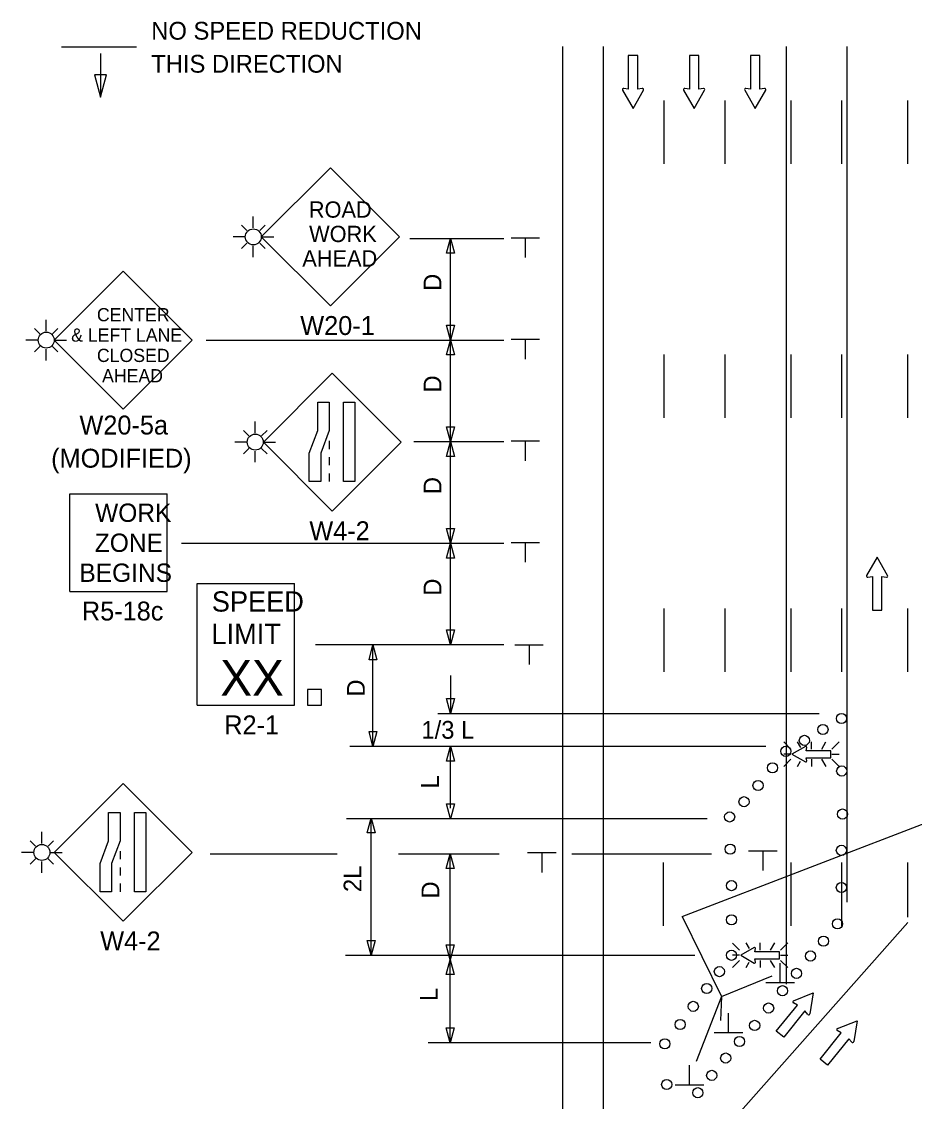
# Model space of a CAD drawing. Extents: x 16726 to 19504, y 5932 to 7446.
# Drawn here: x 16725.6 to 17077.3, y 6450.1 to 6875.1 of the extents above; entities that cross this region are included whole.
import ezdxf

# ---------------------------------------------------------------- set-up
doc = ezdxf.new("R2010")
doc.units = 0
for name, color, linetype in [('ALI_LEGAL_EX', 7, 'Continuous'), ('MT_SCRATCH_LEVEL_E', 7, 'Continuous'), ('PAVT_EDGE_EX', 7, 'Continuous'), ('TRAFFIC_SIGNS_PR', 7, 'Continuous'), ('TYPICAL_EX', 7, 'Continuous'), ('TYPICAL_TEXT_DIMEN_PR', 7, 'Continuous')]:
    doc.layers.add(name, color=color, linetype=linetype)

msp = doc.modelspace()

# ---------------------------------------------------------------- linework, layer by layer
at = {"layer": 'ALI_LEGAL_EX'}
for points in [[(16978.71, 6819.12), (16978.71, 6844.12)], [(17002.71, 6819.12), (17002.71, 6844.12)], [(17028.71, 6819.12), (17028.71, 6844.12)], [(17048.71, 6819.12), (17048.71, 6844.12)], [(17074.71, 6819.12), (17074.71, 6844.12)], [(16978.71, 6719.12), (16978.71, 6744.12)], [(17002.71, 6719.12), (17002.71, 6744.12)], [(17028.71, 6719.12), (17028.71, 6744.12)], [(17048.71, 6719.12), (17048.71, 6744.12)], [(17074.71, 6719.12), (17074.71, 6744.12)], [(16978.71, 6619.12), (16978.71, 6644.12)], [(17002.71, 6619.12), (17002.71, 6644.12)], [(17028.71, 6619.12), (17028.71, 6644.12)], [(17048.71, 6619.12), (17048.71, 6644.12)], [(17074.71, 6619.12), (17074.71, 6644.12)], [(16978.5, 6519.12), (16978.5, 6544.12)], [(17028.71, 6519.12), (17028.71, 6544.12)], [(17048.71, 6519.12), (17048.71, 6544.12)], [(17074.71, 6522.64), (17074.71, 6544.12)]]:
    msp.add_lwpolyline(points, dxfattribs=at)
at = {"layer": 'MT_SCRATCH_LEVEL_E'}
for p, q in [((16968.31, 6861.76), (16964.57, 6861.76)), ((16964.57, 6861.76), (16964.57, 6848.5)), ((16968.31, 6861.76), (16964.57, 6861.76)), ((16964.57, 6861.76), (16964.57, 6848.5)), ((16968.31, 6848.5), (16968.31, 6861.76)), ((16968.31, 6848.5), (16968.31, 6861.76)), ((16992.38, 6861.76), (16988.64, 6861.76)), ((16988.64, 6861.76), (16988.64, 6848.5)), ((16992.38, 6861.76), (16988.64, 6861.76)), ((16988.64, 6861.76), (16988.64, 6848.5)), ((16992.38, 6848.5), (16992.38, 6861.76)), ((16992.38, 6848.5), (16992.38, 6861.76)), ((17016.45, 6861.76), (17012.71, 6861.76)), ((17012.71, 6861.76), (17012.71, 6848.5)), ((17016.45, 6861.76), (17012.71, 6861.76)), ((17012.71, 6861.76), (17012.71, 6848.5)), ((17016.45, 6848.5), (17016.45, 6861.76)), ((17016.45, 6848.5), (17016.45, 6861.76)), ((16962.31, 6848.13), (16966.46, 6840.89)), ((16962.31, 6848.13), (16966.46, 6840.89)), ((16964.57, 6848.5), (16962.79, 6848.82)), ((16964.57, 6848.5), (16962.79, 6848.82)), ((16966.46, 6840.89), (16970.57, 6848.13)), ((16966.46, 6840.89), (16970.57, 6848.13)), ((16970.08, 6848.82), (16968.31, 6848.5)), ((16970.08, 6848.82), (16968.31, 6848.5)), ((16986.38, 6848.13), (16990.53, 6840.89)), ((16986.38, 6848.13), (16990.53, 6840.89)), ((16988.64, 6848.5), (16986.86, 6848.82)), ((16988.64, 6848.5), (16986.86, 6848.82)), ((16990.53, 6840.89), (16994.64, 6848.13)), ((16990.53, 6840.89), (16994.64, 6848.13)), ((16994.16, 6848.82), (16992.38, 6848.5)), ((16994.16, 6848.82), (16992.38, 6848.5)), ((17010.45, 6848.13), (17014.6, 6840.89)), ((17010.45, 6848.13), (17014.6, 6840.89)), ((17012.71, 6848.5), (17010.93, 6848.82)), ((17012.71, 6848.5), (17010.93, 6848.82)), ((17014.6, 6840.89), (17018.71, 6848.13)), ((17014.6, 6840.89), (17018.71, 6848.13)), ((17018.23, 6848.82), (17016.45, 6848.5)), ((17018.23, 6848.82), (17016.45, 6848.5)), ((17062.58, 6664.37), (17058.47, 6657.13)), ((17062.58, 6664.37), (17058.47, 6657.13)), ((17066.73, 6657.13), (17062.58, 6664.37)), ((17066.73, 6657.13), (17062.58, 6664.37)), ((17058.95, 6656.44), (17060.73, 6656.76)), ((17058.95, 6656.44), (17060.73, 6656.76)), ((17060.73, 6656.76), (17060.73, 6643.5)), ((17060.73, 6656.76), (17060.73, 6643.5)), ((17064.47, 6643.5), (17064.47, 6656.76)), ((17064.47, 6656.76), (17066.25, 6656.44)), ((17064.47, 6643.5), (17064.47, 6656.76)), ((17064.47, 6656.76), (17066.25, 6656.44)), ((17060.73, 6643.5), (17064.47, 6643.5)), ((17060.73, 6643.5), (17064.47, 6643.5)), ((17029.66, 6489.71), (17037.44, 6492.75)), ((17029.66, 6489.71), (17037.44, 6492.75)), ((17037.44, 6492.75), (17036.1, 6484.53)), ((17037.44, 6492.75), (17036.1, 6484.53)), ((17022.88, 6477.68), (17031.19, 6488.01)), ((17022.88, 6477.68), (17031.19, 6488.01)), ((17031.19, 6488.01), (17029.61, 6488.88)), ((17031.19, 6488.01), (17029.61, 6488.88)), ((17034.1, 6485.66), (17025.79, 6475.33)), ((17034.1, 6485.66), (17025.79, 6475.33)), ((17035.29, 6484.3), (17034.1, 6485.66)), ((17035.29, 6484.3), (17034.1, 6485.66)), ((17046.96, 6478.77), (17054.73, 6481.8)), ((17046.96, 6478.77), (17054.73, 6481.8)), ((17054.73, 6481.8), (17053.39, 6473.59)), ((17054.73, 6481.8), (17053.39, 6473.59)), ((17025.79, 6475.33), (17022.88, 6477.68)), ((17025.79, 6475.33), (17022.88, 6477.68)), ((17040.17, 6466.74), (17048.49, 6477.06)), ((17040.17, 6466.74), (17048.49, 6477.06)), ((17051.4, 6474.72), (17043.09, 6464.39)), ((17051.4, 6474.72), (17043.09, 6464.39)), ((17048.49, 6477.06), (17046.91, 6477.93)), ((17048.49, 6477.06), (17046.91, 6477.93)), ((17052.59, 6473.36), (17051.4, 6474.72)), ((17052.59, 6473.36), (17051.4, 6474.72)), ((17043.09, 6464.39), (17040.17, 6466.74)), ((17043.09, 6464.39), (17040.17, 6466.74))]:
    msp.add_line(p, q, dxfattribs=at)
for centre, start, end in [((16962.72, 6848.36), 80.0362, 209.7731), ((16962.72, 6848.36), 80.0362, 209.7731), ((16970.16, 6848.36), 330.4248, 99.9638), ((16970.16, 6848.36), 330.4248, 99.9638), ((16986.79, 6848.36), 80.0362, 209.7731), ((16986.79, 6848.36), 80.0362, 209.7731), ((16994.23, 6848.36), 330.4248, 99.9638), ((16994.23, 6848.36), 330.4248, 99.9638), ((17010.86, 6848.36), 80.0362, 209.7731), ((17010.86, 6848.36), 80.0362, 209.7731), ((17018.3, 6848.36), 330.4248, 99.9638), ((17018.3, 6848.36), 330.4248, 99.9638), ((17058.88, 6656.9), 150.4248, 279.9638), ((17058.88, 6656.9), 150.4248, 279.9638), ((17066.32, 6656.9), 260.0362, 29.7731), ((17066.32, 6656.9), 260.0362, 29.7731), ((17029.84, 6489.28), 111.3861, 241.123), ((17029.84, 6489.28), 111.3861, 241.123), ((17035.64, 6484.61), 221.1954, 350.7344), ((17035.64, 6484.61), 221.1954, 350.7344), ((17047.14, 6478.33), 111.3861, 241.123), ((17047.14, 6478.33), 111.3861, 241.123), ((17052.94, 6473.67), 221.1954, 350.7344), ((17052.94, 6473.67), 221.1954, 350.7344)]:
    msp.add_arc(centre, 0.463, start, end, dxfattribs=at)
at = {"layer": 'PAVT_EDGE_EX'}
for p, q in [((16954.71, 6865.32), (16954.71, 6079.93)), ((17026.71, 6865.32), (17026.71, 6496.21)), ((17050.71, 6865.32), (17050.71, 6528.52)), ((17026.71, 6806.67), (17026.71, 6533.65)), ((17050.71, 6806.67), (17050.71, 6536.52)), ((16938.71, 6770.67), (16938.71, 6079.72))]:
    msp.add_line(p, q, dxfattribs=at)
at = {"layer": 'TRAFFIC_SIGNS_PR'}
for p, q in [((16847.23, 6817.6), (16820.04, 6790.41)), ((16874.42, 6790.41), (16847.23, 6817.6)), ((16816.89, 6793.97), (16816.89, 6798.47)), ((16814.38, 6792.93), (16812.27, 6795.03)), ((16819.4, 6792.93), (16821.51, 6795.03)), ((16813.74, 6790.41), (16808.9, 6790.41)), ((16820.04, 6790.41), (16824.92, 6790.41)), ((16820.04, 6790.41), (16847.23, 6763.23)), ((16847.23, 6763.23), (16874.42, 6790.41)), ((16814.37, 6787.9), (16812.27, 6785.79)), ((16816.89, 6782.45), (16816.89, 6786.86)), ((16819.4, 6787.9), (16821.51, 6785.79)), ((16765.67, 6776.93), (16738.48, 6749.74)), ((16792.85, 6749.74), (16765.67, 6776.93)), ((16735.33, 6753.3), (16735.33, 6757.8)), ((16732.81, 6752.26), (16730.71, 6754.36)), ((16737.84, 6752.26), (16739.95, 6754.36)), ((16732.17, 6749.74), (16727.34, 6749.74)), ((16732.81, 6747.23), (16730.71, 6745.12)), ((16735.33, 6741.78), (16735.33, 6746.19)), ((16737.84, 6747.23), (16739.95, 6745.12)), ((16738.48, 6749.74), (16743.36, 6749.74)), ((16738.48, 6749.74), (16765.67, 6722.56)), ((16765.67, 6722.56), (16792.85, 6749.74)), ((16848.01, 6736.74), (16820.86, 6709.59)), ((16875.16, 6709.59), (16848.01, 6736.74)), ((16817.66, 6713.17), (16817.66, 6717.68)), ((16815.14, 6712.13), (16813.04, 6714.24)), ((16820.17, 6712.13), (16822.28, 6714.24)), ((16814.5, 6709.62), (16809.67, 6709.62)), ((16820.81, 6709.62), (16825.69, 6709.62)), ((16820.86, 6709.59), (16848.01, 6682.44)), ((16846.76, 6710.08), (16846.76, 6706.88)), ((16848.01, 6682.44), (16875.16, 6709.59)), ((16815.14, 6707.11), (16813.04, 6705)), ((16817.66, 6701.65), (16817.66, 6706.07)), ((16820.17, 6707.11), (16822.28, 6705)), ((16846.76, 6703.68), (16846.76, 6700.48)), ((16846.76, 6697.28), (16846.76, 6694.08)), ((16744.58, 6650.83), (16744.58, 6689.23)), ((16744.58, 6689.23), (16782.98, 6689.23)), ((16782.98, 6650.83), (16782.98, 6689.23)), ((16794.77, 6654.01), (16833.17, 6654.01)), ((16794.77, 6606.01), (16794.77, 6654.01)), ((16833.17, 6606.01), (16833.17, 6654.01)), ((16744.58, 6650.83), (16782.98, 6650.83)), ((16794.77, 6606.01), (16833.17, 6606.01)), ((17025.79, 6591.61), (17028.61, 6588.79)), ((17032.51, 6589.43), (17031.25, 6591.61)), ((17036.7, 6588.79), (17036.7, 6591.61)), ((17040.83, 6588.79), (17042.46, 6591.61)), ((17044.78, 6588.79), (17047.6, 6591.61)), ((17028.61, 6586.76), (17025.79, 6586.76)), ((17025.79, 6581.91), (17028.61, 6584.73)), ((17036.7, 6584.73), (17036.7, 6581.91)), ((17042.49, 6581.91), (17040.86, 6584.73)), ((17044.78, 6586.76), (17047.6, 6586.76)), ((17044.78, 6584.73), (17047.6, 6581.91)), ((17031.23, 6581.91), (17032.44, 6584)), ((16765.64, 6575.26), (16738.49, 6548.11)), ((16792.8, 6548.11), (16765.64, 6575.26)), ((16733.6, 6551.62), (16733.6, 6556.12)), ((16731.09, 6550.58), (16728.98, 6552.69)), ((16736.12, 6550.58), (16738.23, 6552.69)), ((16730.45, 6548.07), (16725.61, 6548.07)), ((16736.76, 6548.07), (16741.64, 6548.07)), ((16738.49, 6548.11), (16765.64, 6520.96)), ((16764.4, 6548.6), (16764.4, 6545.4)), ((16765.64, 6520.96), (16792.8, 6548.11)), ((16731.09, 6545.55), (16728.98, 6543.45)), ((16733.6, 6540.1), (16733.6, 6544.51)), ((16736.12, 6545.55), (16738.22, 6543.45)), ((16764.4, 6542.2), (16764.4, 6539)), ((16764.4, 6535.8), (16764.4, 6532.6)), ((17005.58, 6512.42), (17008.4, 6509.61)), ((17012.3, 6510.24), (17011.04, 6512.43)), ((17016.49, 6509.61), (17016.49, 6512.43)), ((17020.62, 6509.61), (17022.25, 6512.43)), ((17024.57, 6509.61), (17027.39, 6512.43)), ((17008.4, 6507.57), (17005.58, 6507.57)), ((17005.58, 6502.72), (17008.4, 6505.54)), ((17011.02, 6502.72), (17012.22, 6504.82)), ((17016.49, 6505.54), (17016.49, 6502.72)), ((17022.28, 6502.72), (17020.65, 6505.54)), ((17024.57, 6507.57), (17027.39, 6507.57)), ((17024.57, 6505.54), (17027.39, 6502.72))]:
    msp.add_line(p, q, dxfattribs=at)
for points in [[(16846.76, 6725.33), (16846.76, 6714.15), (16843.42, 6705.26), (16843.42, 6694.08), (16838.92, 6694.08), (16838.92, 6705.26), (16842.27, 6714.15), (16842.27, 6725.33)], [(16856.9, 6725.33), (16856.9, 6694.08), (16852.4, 6694.08), (16852.4, 6725.33)], [(16838.19, 6606.01), (16843.78, 6606.01), (16843.78, 6612.19), (16838.19, 6612.19)], [(16764.4, 6563.85), (16764.4, 6552.67), (16761.05, 6543.78), (16761.05, 6532.6), (16756.56, 6532.6), (16756.56, 6543.78), (16759.9, 6552.67), (16759.9, 6563.85)], [(16774.53, 6563.85), (16774.53, 6532.6), (16770.04, 6532.6), (16770.04, 6563.85)]]:
    msp.add_lwpolyline(points, close=True, dxfattribs=at)
for points in [[(17034.37, 6589.78), (17029.06, 6586.76), (17034.37, 6583.72)], [(17034.87, 6584.08), (17034.64, 6585.37), (17044.36, 6585.37), (17044.36, 6588.12), (17034.64, 6588.12), (17034.87, 6589.42)], [(17014.16, 6510.59), (17008.85, 6507.57), (17014.16, 6504.53)], [(17014.66, 6504.89), (17014.43, 6506.19), (17024.15, 6506.19), (17024.15, 6508.93), (17014.43, 6508.93), (17014.66, 6510.24)]]:
    msp.add_lwpolyline(points, dxfattribs=at)
for centre, radius in [((16816.89, 6790.41), 3.15), ((16735.33, 6749.74), 3.15), ((16817.66, 6709.62), 3.15), ((17048.6, 6600.8), 2), ((17048.6, 6600.8), 2), ((17041.27, 6596.49), 2), ((17033.94, 6592.19), 2), ((17026.61, 6587.88), 2), ((17021.41, 6581.36), 2), ((17048.65, 6580.13), 2), ((17015.7, 6574.44), 2), ((17010.17, 6568.05), 2), ((17004.51, 6562.04), 2), ((17048.96, 6563.18), 2), ((16733.6, 6548.07), 3.15), ((17004.71, 6549.39), 2), ((17048.52, 6548.9), 2), ((17005.21, 6535), 2), ((17005.21, 6535), 2), ((17048.52, 6534.26), 2), ((17005.21, 6521.52), 2), ((17046.98, 6520), 2), ((17041.48, 6513.17), 2), ((17005.21, 6507.59), 2), ((17036.36, 6507.3), 2), ((17000.47, 6501.15), 2), ((17030.86, 6500.47), 2), ((16995.48, 6494.51), 2), ((17025.36, 6493.64), 2), ((16990.19, 6487.48), 2), ((17019.86, 6486.81), 2), ((16984.99, 6480.37), 2), ((17014.36, 6479.98), 2), ((17014.36, 6479.98), 2), ((16978.97, 6472.76), 2), ((17008.42, 6473.62), 2), ((17002.95, 6467.14), 2), ((16997.45, 6460.31), 2), ((16979.71, 6456.72), 2), ((16991.95, 6453.48), 2)]:
    msp.add_circle(centre, radius, dxfattribs=at)
for centre, start, end in [((17034.53, 6589.48), 350.7308, 118.8916), ((17034.53, 6584.02), 241.4833, 9.9593), ((17014.32, 6510.29), 350.7308, 118.8916), ((17014.32, 6504.83), 241.4833, 9.9593)]:
    msp.add_arc(centre, 0.341, start, end, dxfattribs=at)
at = {"layer": 'TYPICAL_EX'}
msp.add_line((16938.71, 6865.32), (16938.71, 6080.34), dxfattribs=at)
at = {"layer": 'TYPICAL_TEXT_DIMEN_PR'}
for p, q in [((16770.83, 6865.03), (16741.4, 6865.03)), ((16756.66, 6862.53), (16756.66, 6845.41)), ((16756.66, 6854.2), (16754.3, 6854.2)), ((16754.3, 6854.2), (16756.66, 6845.41)), ((16756.66, 6845.41), (16759.02, 6854.2)), ((16759.02, 6854.2), (16756.66, 6854.2)), ((16878.53, 6789.8), (16915.61, 6789.8)), ((16893.04, 6783.94), (16894.61, 6789.8)), ((16894.61, 6789.8), (16896.18, 6783.94)), ((16894.61, 6749.8), (16894.61, 6789.8)), ((16918.4, 6790.07), (16929.65, 6790.07)), ((16924.03, 6790.07), (16924.03, 6782.29)), ((16894.61, 6783.94), (16893.04, 6783.94)), ((16896.18, 6783.94), (16894.61, 6783.94)), ((16894.61, 6749.8), (16893.04, 6755.66)), ((16893.04, 6755.66), (16894.61, 6755.66)), ((16894.61, 6755.66), (16896.18, 6755.66)), ((16896.18, 6755.66), (16894.61, 6749.8)), ((16798.35, 6749.8), (16915.61, 6749.8)), ((16893.04, 6743.94), (16894.61, 6749.8)), ((16894.61, 6749.8), (16896.18, 6743.94)), ((16894.61, 6709.8), (16894.61, 6749.8)), ((16918.4, 6750.07), (16929.65, 6750.07)), ((16924.03, 6750.07), (16924.03, 6742.29)), ((16894.61, 6743.94), (16893.04, 6743.94)), ((16896.18, 6743.94), (16894.61, 6743.94)), ((16894.61, 6709.8), (16893.04, 6715.66)), ((16893.04, 6715.66), (16894.61, 6715.66)), ((16894.61, 6715.66), (16896.18, 6715.66)), ((16896.18, 6715.66), (16894.61, 6709.8)), ((16880.05, 6709.8), (16915.61, 6709.8)), ((16893.04, 6703.94), (16894.61, 6709.8)), ((16894.61, 6709.8), (16896.18, 6703.94)), ((16894.61, 6669.8), (16894.61, 6709.8)), ((16918.4, 6710.07), (16929.65, 6710.07)), ((16924.03, 6710.07), (16924.03, 6702.29)), ((16894.61, 6703.94), (16893.04, 6703.94)), ((16896.18, 6703.94), (16894.61, 6703.94)), ((16894.61, 6669.8), (16893.04, 6675.66)), ((16893.04, 6675.66), (16894.61, 6675.66)), ((16894.61, 6675.66), (16896.18, 6675.66)), ((16896.18, 6675.66), (16894.61, 6669.8)), ((16788.55, 6669.8), (16915.61, 6669.8)), ((16893.04, 6663.94), (16894.61, 6669.8)), ((16894.61, 6669.8), (16896.18, 6663.94)), ((16894.61, 6629.8), (16894.61, 6669.8)), ((16918.4, 6670.07), (16929.65, 6670.07)), ((16924.03, 6670.07), (16924.03, 6662.29)), ((16894.61, 6663.94), (16893.04, 6663.94)), ((16896.18, 6663.94), (16894.61, 6663.94)), ((16894.61, 6629.8), (16893.04, 6635.66)), ((16893.04, 6635.66), (16894.61, 6635.66)), ((16894.61, 6635.66), (16896.18, 6635.66)), ((16896.18, 6635.66), (16894.61, 6629.8)), ((16915.61, 6629.8), (16841.38, 6629.8)), ((16862.46, 6623.94), (16864.03, 6629.8)), ((16864.03, 6629.8), (16865.6, 6623.94)), ((16864.03, 6590.05), (16864.03, 6629.8)), ((16919.86, 6629.8), (16931.11, 6629.8)), ((16925.49, 6629.8), (16925.49, 6622.02)), ((16864.03, 6623.94), (16862.46, 6623.94)), ((16865.6, 6623.94), (16864.03, 6623.94)), ((16894.61, 6617.73), (16894.61, 6602.8)), ((16894.61, 6602.8), (16893.04, 6608.67)), ((16893.04, 6608.67), (16894.61, 6608.67)), ((16894.61, 6608.67), (16896.18, 6608.67)), ((16896.18, 6608.67), (16894.61, 6602.8)), ((16889.61, 6602.8), (17039.81, 6602.8)), ((16864.03, 6589.79), (16862.46, 6595.65)), ((16862.46, 6595.65), (16864.03, 6595.65)), ((16864.03, 6595.65), (16865.6, 6595.65)), ((16865.6, 6595.65), (16864.03, 6589.79)), ((16985.82, 6522.8), (17170.38, 6593.93)), ((17018.77, 6589.8), (16854.92, 6589.8)), ((16893.04, 6584.03), (16894.61, 6589.9)), ((16894.61, 6589.9), (16896.18, 6584.03)), ((16894.61, 6565.46), (16894.61, 6589.57)), ((16894.61, 6584.03), (16893.04, 6584.03)), ((16896.18, 6584.03), (16894.61, 6584.03)), ((16894.61, 6561.36), (16893.04, 6567.22)), ((16893.04, 6567.22), (16894.61, 6567.22)), ((16894.61, 6567.22), (16896.18, 6567.22)), ((16896.18, 6567.22), (16894.61, 6561.36)), ((16853.65, 6561.39), (16995.64, 6561.39)), ((16861.73, 6555.76), (16863.3, 6561.62)), ((16863.3, 6561.62), (16864.87, 6555.76)), ((16863.3, 6507.59), (16863.3, 6561.55)), ((16863.3, 6555.76), (16861.73, 6555.76)), ((16864.87, 6555.76), (16863.3, 6555.76)), ((16799.85, 6547.59), (16849.95, 6547.59)), ((16874.02, 6547.59), (16913.67, 6547.59)), ((16892.83, 6541.73), (16894.4, 6547.59)), ((16894.4, 6505.69), (16894.4, 6547.59)), ((16894.4, 6547.59), (16895.97, 6541.73)), ((16924.9, 6548.01), (16936.15, 6548.01)), ((16930.52, 6548.01), (16930.52, 6540.22)), ((16942.36, 6547.59), (16997.31, 6547.59)), ((17011.92, 6548.77), (17023.17, 6548.77)), ((17017.55, 6548.77), (17017.55, 6540.99)), ((16894.4, 6541.73), (16892.83, 6541.73)), ((16895.97, 6541.73), (16894.4, 6541.73)), ((16985.82, 6522.8), (17001.34, 6491.32)), ((17002.71, 6439.27), (17074.68, 6520.48)), ((16863.3, 6507.59), (16861.73, 6513.45)), ((16861.73, 6513.45), (16863.3, 6513.45)), ((16863.3, 6513.45), (16864.87, 6513.45)), ((16864.87, 6513.45), (16863.3, 6507.59)), ((16894.42, 6505.78), (16892.85, 6511.65)), ((16892.85, 6511.65), (16894.42, 6511.65)), ((16894.42, 6511.65), (16895.99, 6511.65)), ((16895.99, 6511.65), (16894.42, 6505.78)), ((16853.25, 6507.59), (16990.78, 6507.59)), ((16892.84, 6499.97), (16894.41, 6505.83)), ((16894.4, 6473.12), (16894.4, 6505.4)), ((16894.41, 6505.83), (16895.98, 6499.97)), ((17024.4, 6496.72), (17024.4, 6504.51)), ((16894.41, 6499.97), (16892.84, 6499.97)), ((16895.98, 6499.97), (16894.41, 6499.97)), ((17001.34, 6491.32), (17021.29, 6499.56)), ((17030.03, 6496.72), (17018.78, 6496.72)), ((17001.34, 6491.32), (16991.36, 6465.71)), ((17001.34, 6491.32), (17000.9, 6481.9)), ((17004.01, 6477.01), (17004.01, 6484.8)), ((16894.41, 6473.11), (16892.84, 6478.97)), ((16892.84, 6478.97), (16894.41, 6478.97)), ((16894.41, 6478.97), (16895.98, 6478.97)), ((16895.98, 6478.97), (16894.41, 6473.11)), ((17009.64, 6477.01), (16998.39, 6477.01)), ((16885.76, 6473.24), (16973.48, 6473.24)), ((16988.71, 6456.51), (16988.71, 6464.29)), ((16994.33, 6456.51), (16983.08, 6456.51))]:
    msp.add_line(p, q, dxfattribs=at)

# ---------------------------------------------------------------- texts
at = {"layer": 'TRAFFIC_SIGNS_PR'}
for s, height, p in [('ROAD', 6.408, (16838.76, 6797.96)), ('WORK', 6.408, (16838.87, 6788.35)), ('AHEAD', 6.408, (16836.18, 6778.73)), ('CENTER', 5.206, (16755.29, 6757.16)), ('W20-1', 7.449, (16835.38, 6751.77)), ('& LEFT LANE', 5.2065, (16745.14, 6749.15)), ('CLOSED', 5.206, (16755.29, 6741.14)), ('AHEAD', 5.206, (16757.32, 6733.13)), ('W20-5a', 7.449, (16748.41, 6712.6)), ('(MODIFIED)', 7.449, (16737.25, 6699.54)), ('WORK', 7.217, (16754.58, 6678.2)), ('W4-2', 7.44, (16838.97, 6671)), ('ZONE', 7.217, (16754.46, 6666.38)), ('BEGINS', 7.217, (16748.39, 6654.58)), ('SPEED', 8, (16800.54, 6642.88)), ('R5-18c', 7.44, (16749.39, 6639.39)), ('LIMIT', 8, (16800.38, 6630.08)), ('XX', 14.031, (16803.88, 6609.77)), ('R2-1', 7.44, (16805.45, 6594.57)), ('W4-2', 7.44, (16756.6, 6509.52))]:
    msp.add_text(s, height=height, dxfattribs=at).set_placement(p)
at = {"layer": 'TYPICAL_TEXT_DIMEN_PR'}
for s, p in [('NO SPEED REDUCTION', (16776.68, 6868.04)), ('THIS DIRECTION', (16776.68, 6855.04)), ('1/3 L', (16883.1, 6592.83))]:
    msp.add_text(s, height=7, dxfattribs=at).set_placement(p)
for s, p in [('D', (16890.97, 6769.12)), ('D', (16890.97, 6729.12)), ('D', (16890.97, 6689.12)), ('D', (16890.97, 6649.12)), ('D', (16860.8, 6609.4)), ('L', (16889.97, 6573.22)), ('2L', (16859.48, 6532.48)), ('D', (16890.15, 6529.91)), ('L', (16889.53, 6489.56))]:
    msp.add_text(s, height=7, rotation=90, dxfattribs=at).set_placement(p)

doc.saveas('drawing.dxf')
